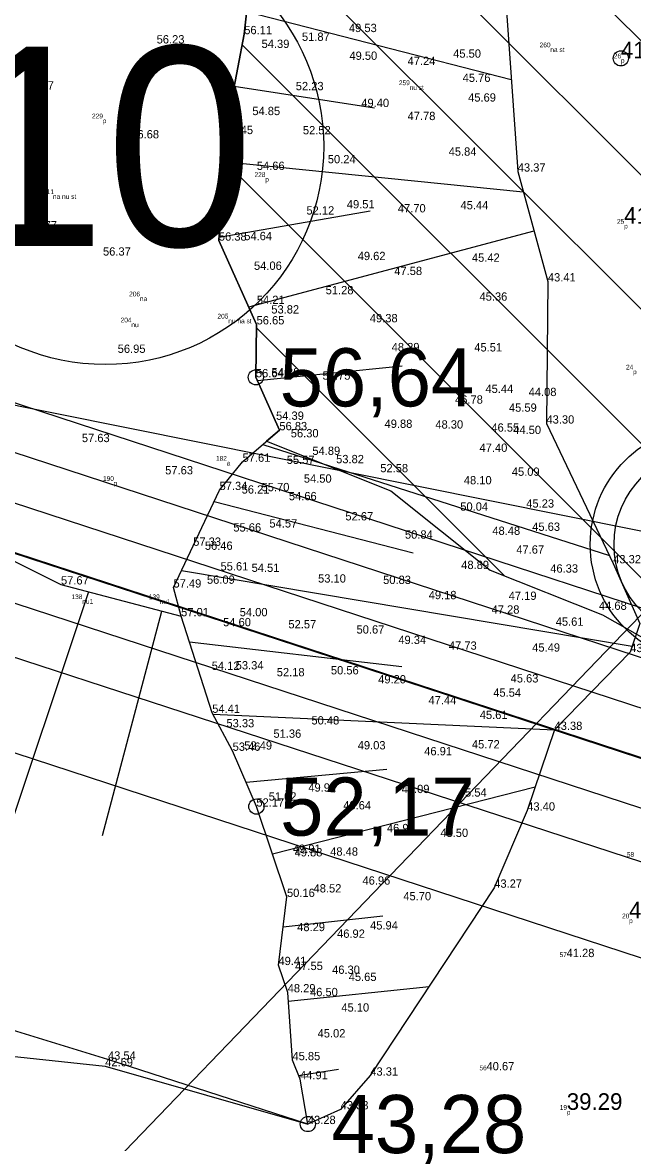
# Model space of a CAD drawing. Extents: x 700746 to 706058, y 6570320 to 6580460.
# Drawn here: x 702872.73 to 702898.47, y 6577258.09 to 6577305.34 of the extents above; entities that cross this region are included whole.
import ezdxf

# ---------------------------------------------------------------- set-up
doc = ezdxf.new("R2010")
doc.units = 0
for name, color, linetype in [('GEOLPUNKT', 7, 'Continuous'), ('illumineerimisjooned', 7, 'Continuous'), ('Kaevandatud ala', 7, 'Continuous'), ('kataster', 7, 'Continuous'), ('KORGUS-EH2000', 7, 'Continuous'), ('Lõige', 7, 'Continuous'), ('maeeraldised_kehtivad', 7, 'Continuous'), ('MOOTKOOD', 7, 'Continuous'), ('MOOTKORG-EH2000', 7, 'Continuous'), ('MOOTNR', 7, 'Continuous'), ('mäeeraldis', 7, 'Continuous'), ('mäeeraldise teenindusmaa', 7, 'Continuous'), ('PIIR', 7, 'Continuous'), ('Plokid', 7, 'Continuous'), ('RELJEEF', 7, 'Continuous'), ('Tmaad_maeeraldised_kehtivad', 7, 'Continuous'), ('VEEKOGU', 7, 'Continuous'), ('VWX2_MV_PLOKK', 7, 'Continuous')]:
    doc.layers.add(name, color=color, linetype=linetype)

msp = doc.modelspace()

# ---------------------------------------------------------------- linework, layer by layer
at = {"layer": 'GEOLPUNKT'}
for radius in [5, 4]:
    msp.add_circle((702901.645, 6577283.339), radius, dxfattribs=at)
at = {"layer": 'illumineerimisjooned'}
for points in [[(702862.311, 6577373.596), (702850.89, 6577377.293), (702839.79, 6577379.563), (702831.646, 6577378.473), (702820.821, 6577374.823), (702754.92, 6577346.017), (702742.145, 6577342.939), (702732.615, 6577342.189), (702714.765, 6577344.588), (702715.658, 6577336.409), (703090.802, 6577213.589), (703232.719, 6577108.158), (703252.344, 6577093.719)], [(702976.891, 6576643.26), (702915.328, 6577059.558), (702785.772, 6577104.455), (702748.407, 6577249.47), (702721.642, 6577298.043), (702716.252, 6577332.033), (702861.102, 6577284.56), (703066.328, 6577217.365), (703088.858, 6577210.018), (703169.031, 6577150.466), (703230.271, 6577104.95), (703275.453, 6577071.675), (703358.033, 6576531.935)], [(703167.053, 6577159.433), (703091.733, 6577215.389), (702863.784, 6577290.018)], [(703290.041, 6576963.147), (703188.508, 6577001.438), (703016.934, 6577112.515), (702852.033, 6577230.395), (702862.776, 6577281.723), (703065.707, 6577215.464), (703087.928, 6577208.218), (703167.838, 6577148.861), (703229.081, 6577103.342), (703273.601, 6577070.555), (703290.041, 6576963.147)]]:
    msp.add_lwpolyline(points, dxfattribs=at)
at = {"layer": 'Kaevandatud ala'}
for p, q in [((702885.692, 6577317.651), (702961.786, 6577241.557)), ((702883.741, 6577313.945), (702957.002, 6577240.684)), ((702883.182, 6577308.847), (702952.218, 6577239.811)), ((702881.984, 6577304.388), (702946.502, 6577239.87)), ((702881.203, 6577299.512), (702938.426, 6577242.289)), ((702882.588, 6577292.47), (702893.053, 6577282.005))]:
    msp.add_line(p, q, dxfattribs=at)
for points in [[(702898.59, 6577340.48), (702896.67, 6577335.54), (702895.42, 6577329.91), (702892.39, 6577327.68), (702892.37, 6577325.56), (702890.6, 6577323.46), (702888.61, 6577321.22), (702886.48, 6577319.78), (702885.8, 6577318.02), (702885.43, 6577316.76), (702884.62, 6577315.21), (702883.8, 6577314.33), (702883.53, 6577312.58), (702883.4, 6577310.62), (702883.11, 6577308.26), (702882.2, 6577307.5), (702882.23, 6577306.39), (702882.07, 6577304.84), (702881.27, 6577300.63), (702881, 6577296.14), (702882.59, 6577292.61), (702882.56, 6577290.38), (702883.55, 6577288.15), (702883.006, 6577287.683)], [(702883.006, 6577287.683), (702888.247, 6577285.595), (702892.428, 6577282.254), (702897.16, 6577280.37), (702901.941, 6577277.664), (702901.603, 6577275.308), (702911.185, 6577268.859), (702910.984, 6577262.539), (702910.646, 6577251.884), (702919.266, 6577249.854), (702923.239, 6577243.427), (702932.999, 6577245.456), (702942.381, 6577239.981), (702951.761, 6577239.728), (702966.129, 6577242.349), (702973.059, 6577233.977), (702979.82, 6577236.43), (702989.2, 6577237.36), (702992.919, 6577234.147), (702996.289, 6577226.894), (703003.652, 6577221.631), (703013.709, 6577214.443)]]:
    msp.add_lwpolyline(points, dxfattribs=at)
at = {"layer": 'kataster'}
msp.add_lwpolyline([(702754.28, 6577347.92), (702820.1, 6577376.69), (702831.19, 6577380.43), (702839.86, 6577381.59), (702851.4, 6577379.23), (702863.2, 6577375.41), (702878.06, 6577370.59), (702900.72, 6577367.74), (702944.77, 6577367.92), (702961.68, 6577364.05), (703005.04, 6577344.66), (703019.19, 6577342.06), (703041.25, 6577339.7), (703057.1, 6577329.85), (703096.08, 6577280.59), (703119.31, 6577233.95), (703129.16, 6577218.59), (703141.54, 6577201.64), (703167.04, 6577172.32), (703168.73, 6577170.37), (703277.36, 6577072.83), (703231.53, 6577106.55), (703089.87, 6577211.79), (702713.81, 6577334.91)], dxfattribs=at)
msp.add_lwpolyline([(702852.27, 6575508.89), (702837.26, 6575620.73), (702848.38, 6575976.59), (702782.85, 6576063.35), (702782.57, 6576096.37), (702842.53, 6576210.56), (702853.4, 6576267.5), (702844.46, 6576489.93), (702877.29, 6576548.25), (702974.72, 6576643.9), (702913.57, 6577058.07), (702784.04, 6577102.84), (702746.48, 6577248.7), (702719.69, 6577297.36), (702713.81, 6577334.91), (703089.87, 6577211.79), (703231.53, 6577106.55), (703277.36, 6577072.83), (703360.09, 6576531.99), (703311.6, 6576228.52), (703293.62, 6575965.66), (703298.84, 6575573.29)], close=True, dxfattribs=at)
at = {"layer": 'KORGUS-EH2000'}
for centre in [(702897.935, 6577303.823), (702882.56, 6577290.38), (702882.58, 6577272.29), (702884.75, 6577258.91)]:
    msp.add_circle(centre, 0.32, dxfattribs=at)
at = {"layer": 'Lõige'}
for points in [[(702834.687, 6577213.734), (702849.883, 6577229.558), (702901.645, 6577283.339), (702934.372, 6577351.305), (702933.752, 6577409.378), (702972.502, 6577440.12), (702995.067, 6577474.124)], [(702840.34, 6577295.661), (702901.645, 6577283.339), (702991.177, 6577252.569), (703074.081, 6577220.567), (703131.906, 6577226.463), (703178.085, 6577224.803)]]:
    msp.add_lwpolyline(points, dxfattribs=at)
at = {"layer": 'maeeraldised_kehtivad'}
msp.add_lwpolyline([(702849.808, 6577229.527), (702861.724, 6577286.461), (703066.949, 6577219.266), (703089.789, 6577211.819), (703170.224, 6577152.072), (703231.46, 6577106.558), (703277.305, 6577072.795), (703294.683, 6576959.259), (703187.602, 6576999.642), (703015.809, 6577110.861)], close=True, dxfattribs=at)
at = {"layer": 'mäeeraldis'}
msp.add_lwpolyline([(702859.802, 6577465.696), (703119.425, 6577442.241), (703125.486, 6577438.859), (703125.878, 6577438.438), (703152.852, 6577264.176), (703167.04, 6577172.32), (703167.079, 6577172.263), (703170.22, 6577152.098), (703089.87, 6577211.79), (702861.725, 6577286.484), (702863.214, 6577375.336), (702862.386, 6577440.049), (702862.38, 6577440.109), (702862.38, 6577440.12), (702859.802, 6577465.696)], dxfattribs=at)
at = {"layer": 'mäeeraldise teenindusmaa'}
msp.add_lwpolyline([(702859.8, 6577465.72), (703125.43, 6577441.71), (703167.04, 6577172.32), (703168.73, 6577170.37), (703277.36, 6577072.83), (703231.53, 6577106.55), (703089.87, 6577211.79), (702713.81, 6577334.91), (702712.5, 6577346.91), (702732.67, 6577344.2), (702741.83, 6577344.92), (702754.28, 6577347.92), (702820.1, 6577376.69), (702831.19, 6577380.43), (702839.86, 6577381.59), (702851.4, 6577379.23), (702863.2, 6577375.41), (702862.38, 6577440.12), (702859.8, 6577465.72)], dxfattribs=at)
at = {"layer": 'PIIR'}
msp.add_circle((702876.218, 6577300.118), 9.2, dxfattribs=at)
at = {"layer": 'Plokid'}
msp.add_lwpolyline([(703043.339, 6577445.098), (703121.898, 6577438.001), (703148.899, 6577263.565), (703163.227, 6577170.805), (703163.267, 6577170.746), (703164.325, 6577163.951), (703092.665, 6577217.188), (702865.809, 6577291.46), (702867.214, 6577375.329), (702866.384, 6577440.28), (702866.378, 6577440.34), (702866.377, 6577440.346), (702864.268, 6577461.276), (703043.339, 6577445.098)], dxfattribs=at)
msp.add_lwpolyline([(703287.547, 6576966.226), (703189.415, 6577003.234), (703018.06, 6577114.169), (702854.258, 6577231.263), (702863.9, 6577277.331), (703064.465, 6577211.662), (703086.067, 6577204.618), (703165.453, 6577145.65), (703226.702, 6577100.127), (703272.178, 6577066.636)], close=True, dxfattribs=at)
at = {"layer": 'RELJEEF'}
for p, q in [((702882.168, 6577305.791), (702893.32, 6577302.93)), ((702887.559, 6577301.73), (702881.651, 6577302.635)), ((702881.2, 6577299.473), (702893.824, 6577298.196)), ((702887.377, 6577297.381), (702881.008, 6577296.279)), ((702882.257, 6577293.349), (702894.276, 6577296.549)), ((702888.728, 6577290.853), (702882.625, 6577290.235)), ((702882.852, 6577287.551), (702897.454, 6577282.867)), ((702889.186, 6577282.971), (702880.799, 6577285.14)), ((702879.433, 6577282.246), (702898.417, 6577279.056)), ((702875.506, 6577281.344), (702869.087, 6577262.109)), ((702876.096, 6577271.075), (702878.599, 6577280.525)), ((702888.714, 6577278.176), (702879.761, 6577279.22)), ((702880.753, 6577276.179), (702895.14, 6577275.52)), ((702888.074, 6577273.857), (702882.149, 6577273.303)), ((702883.253, 6577270.302), (702894.331, 6577273.129)), ((702887.909, 6577267.668), (702883.711, 6577267.213)), ((702883.926, 6577264.091), (702889.855, 6577264.705)), ((702886.043, 6577261.211), (702884.361, 6577260.947)), ((702884.75, 6577258.91), (702884.75, 6577258.91))]:
    msp.add_line(p, q, dxfattribs=at)
for points in [[(702884.75, 6577258.91), (702884.42, 6577260.8), (702884.1, 6577261.6), (702883.9, 6577264.46), (702883.51, 6577265.61), (702883.87, 6577268.48), (702882.58, 6577272.29), (702881.58, 6577274.64), (702880.72, 6577276.24), (702879.41, 6577280.31), (702879.09, 6577281.52), (702879.92, 6577283.28), (702881.03, 6577285.63), (702882, 6577286.82), (702883.55, 6577288.15), (702882.56, 6577290.38), (702882.59, 6577292.61), (702881, 6577296.14), (702881.27, 6577300.63), (702882.07, 6577304.84), (702882.23, 6577306.39)], [(702884.75, 6577258.91), (702884.42, 6577260.8), (702884.1, 6577261.6), (702883.9, 6577264.46), (702883.51, 6577265.61), (702883.87, 6577268.48), (702882.58, 6577272.29), (702881.58, 6577274.64), (702880.72, 6577276.24), (702879.41, 6577280.31), (702879.09, 6577281.52), (702879.92, 6577283.28), (702881.03, 6577285.63), (702882, 6577286.82), (702883.55, 6577288.15), (702882.56, 6577290.38), (702882.59, 6577292.61), (702881, 6577296.14), (702881.27, 6577300.63), (702882.07, 6577304.84), (702882.23, 6577306.39)], [(702739.023, 6577231.907), (702738.829, 6577234.118), (702736.843, 6577244.166), (702737.449, 6577253.091), (702740.127, 6577260.7), (702744.086, 6577271.721), (702753.189, 6577289.269), (702762.956, 6577297.622), (702781.322, 6577304.452), (702803.109, 6577295.631), (702808.823, 6577292.731), (702816.396, 6577293.218), (702820.373, 6577296.135), (702836.414, 6577289.932), (702856.388, 6577286.327), (702857.99, 6577287.14), (702860.42, 6577287.06), (702862.6, 6577287.41), (702864.79, 6577286.08), (702869.15, 6577284.23), (702874.35, 6577281.65), (702879.41, 6577280.31)], [(702788.861, 6577235.978), (702797.028, 6577259.824), (702799.555, 6577268.407), (702805.282, 6577267.438), (702829.907, 6577267.309), (702860.829, 6577262.996), (702876.211, 6577261.343), (702884.75, 6577258.91)]]:
    msp.add_lwpolyline(points, dxfattribs=at)
at = {"layer": 'Tmaad_maeeraldised_kehtivad'}
msp.add_lwpolyline([(702974.764, 6576643.974), (702913.527, 6577058.065), (702784.103, 6577102.917), (702746.534, 6577248.726), (702719.722, 6577297.384), (702713.764, 6577334.953), (702861.724, 6577286.461), (703066.949, 6577219.266), (703089.789, 6577211.819), (703089.789, 6577211.819), (703170.224, 6577152.072), (703231.46, 6577106.558), (703277.305, 6577072.795), (703360.057, 6576531.928)], dxfattribs=at)
at = {"layer": 'VEEKOGU'}
for points in [[(702899.52, 6577319.43), (702898.02, 6577316.02), (702896.85, 6577313.28), (702894.87, 6577309.23), (702893.12, 6577305.81), (702893.59, 6577299.05), (702894.86, 6577294.42), (702894.8, 6577288.43), (702897.61, 6577282.54), (702898.74, 6577280.01), (702898.33, 6577278.8), (702895.14, 6577275.52), (702893.99, 6577272.12), (702892.6, 6577268.87), (702887.38, 6577260.95), (702886.13, 6577259.53)], [(702899.52, 6577319.43), (702898.02, 6577316.02), (702896.85, 6577313.28), (702894.87, 6577309.23), (702893.12, 6577305.81), (702893.59, 6577299.05), (702894.86, 6577294.42), (702894.8, 6577288.43), (702897.61, 6577282.54), (702898.74, 6577280.01), (702898.33, 6577278.8), (702895.14, 6577275.52), (702893.99, 6577272.12), (702892.6, 6577268.87), (702887.38, 6577260.95), (702886.13, 6577259.53)], [(702886.13, 6577259.53), (702884.75, 6577258.91), (702876.329, 6577261.625), (702872.126, 6577262.92), (702866.842, 6577263.801), (702863.234, 6577263.318), (702860.829, 6577262.996), (702858.855, 6577263.15), (702853.034, 6577263.204), (702848.147, 6577263.29), (702841.101, 6577265.479), (702833.134, 6577264.702), (702830.471, 6577264.031), (702826.548, 6577262.778), (702820.531, 6577264.171), (702818.095, 6577266.211), (702814.068, 6577266.459)], [(702886.13, 6577259.53), (702884.75, 6577258.91), (702876.329, 6577261.625), (702872.126, 6577262.92), (702866.842, 6577263.801), (702863.234, 6577263.318), (702860.829, 6577262.996), (702858.855, 6577263.15), (702853.034, 6577263.204), (702848.147, 6577263.29), (702841.101, 6577265.479), (702833.134, 6577264.702), (702830.471, 6577264.031), (702826.548, 6577262.778), (702820.531, 6577264.171), (702818.095, 6577266.211), (702814.068, 6577266.459)]]:
    msp.add_lwpolyline(points, dxfattribs=at)
at = {"layer": 'VWX2_MV_PLOKK'}
for points in [[(702859.74, 6577465.7), (703125.37, 6577441.7), (703167.08, 6577172.26), (703170.22, 6577152.07), (703089.79, 6577211.82), (702861.72, 6577286.46), (702863.21, 6577375.33), (702862.39, 6577440.05)], [(702859.74, 6577465.7), (703125.37, 6577441.7), (703167.08, 6577172.26), (703170.22, 6577152.07), (703089.79, 6577211.82), (702861.72, 6577286.46), (702863.21, 6577375.33), (702862.39, 6577440.05)], [(702849.88, 6577229.56), (702861.72, 6577286.46), (703066.96, 6577219.29), (703089.79, 6577211.82), (703170.22, 6577152.07), (703231.53, 6577106.55), (703277.36, 6577072.83), (703294.74, 6576959.21), (703187.67, 6576999.67), (703015.74, 6577110.88)], [(702849.88, 6577229.56), (702861.72, 6577286.46), (703066.96, 6577219.29), (703089.79, 6577211.82), (703170.22, 6577152.07), (703231.53, 6577106.55), (703277.36, 6577072.83), (703294.74, 6576959.21), (703187.67, 6576999.67), (703015.74, 6577110.88)]]:
    msp.add_lwpolyline(points, close=True, dxfattribs=at)

# ---------------------------------------------------------------- texts
at = {"layer": 'KORGUS-EH2000'}
for s, p in [('56,64', (702883.56, 6577289.155)), ('52,17', (702883.58, 6577271.065)), ('43,28', (702885.75, 6577257.685))]:
    msp.add_text(s, height=2.45, dxfattribs=at).set_placement(p)
at = {"layer": 'MOOTKOOD'}
for s, p in [('na st', (702894.964, 6577304.089)), ('p', (702897.935, 6577303.623)), ('nu st', (702889.037, 6577302.493)), ('p', (702876.11, 6577301.092)), ('p', (702882.956, 6577298.621)), ('na nu st', (702874.01, 6577297.902)), ('p', (702898.071, 6577296.652)), ('na', (702877.673, 6577293.592)), ('nu na st', (702881.397, 6577292.657)), ('nu', (702877.314, 6577292.495)), ('p', (702898.448, 6577290.51)), ('a', (702881.329, 6577286.665)), ('p', (702876.572, 6577285.815)), ('nu1', (702875.247, 6577280.834)), ('nu1', (702878.506, 6577280.83)), ('p', (702898.281, 6577267.379)), ('p', (702895.657, 6577259.309))]:
    msp.add_text(s, height=0.2, dxfattribs=at).set_placement(p)
at = {"layer": 'MOOTKORG-EH2000'}
for s, height, p in [('56.11', 0.35, (702882.07, 6577304.84)), ('49.53', 0.35, (702886.48, 6577304.93)), ('56.23', 0.35, (702878.38, 6577304.45)), ('54.39', 0.35, (702882.8, 6577304.26)), ('51.87', 0.35, (702884.5, 6577304.56)), ('41.24', 0.7, (702897.935, 6577303.823)), ('49.50', 0.35, (702886.5, 6577303.76)), ('45.50', 0.35, (702890.87, 6577303.85)), ('47.24', 0.35, (702888.95, 6577303.54)), ('45.76', 0.35, (702891.27, 6577302.83)), ('57.07', 0.35, (702872.88, 6577302.51)), ('52.23', 0.35, (702884.24, 6577302.48)), ('45.69', 0.35, (702891.5, 6577302)), ('54.85', 0.35, (702882.41, 6577301.43)), ('49.40', 0.35, (702887, 6577301.77)), ('47.78', 0.35, (702888.95, 6577301.22)), ('56.68', 0.35, (702877.31, 6577300.45)), ('56.45', 0.35, (702881.27, 6577300.63)), ('52.52', 0.35, (702884.54, 6577300.62)), ('45.84', 0.35, (702890.68, 6577299.72)), ('54.66', 0.35, (702882.6, 6577299.12)), ('50.24', 0.35, (702885.59, 6577299.4)), ('43.37', 0.35, (702893.59, 6577299.05)), ('52.12', 0.35, (702884.69, 6577297.24)), ('49.51', 0.35, (702886.39, 6577297.5)), ('47.70', 0.35, (702888.54, 6577297.33)), ('45.44', 0.35, (702891.18, 6577297.46)), ('41.35', 0.7, (702898.071, 6577296.852)), ('56.77', 0.35, (702873.01, 6577296.62)), ('56.38', 0.35, (702881, 6577296.14)), ('54.64', 0.35, (702882.07, 6577296.16)), ('56.37', 0.35, (702876.12, 6577295.51)), ('49.62', 0.35, (702886.85, 6577295.32)), ('45.42', 0.35, (702891.66, 6577295.25)), ('54.06', 0.35, (702882.48, 6577294.91)), ('47.58', 0.35, (702888.39, 6577294.69)), ('43.41', 0.35, (702894.86, 6577294.42)), ('51.28', 0.35, (702885.5, 6577293.88)), ('54.21', 0.35, (702882.6, 6577293.47)), ('45.36', 0.35, (702891.98, 6577293.61)), ('53.82', 0.35, (702883.21, 6577293.07)), ('56.65', 0.35, (702882.59, 6577292.61)), ('49.38', 0.35, (702887.36, 6577292.7)), ('56.95', 0.35, (702876.74, 6577291.41)), ('48.29', 0.35, (702888.28, 6577291.48)), ('45.51', 0.35, (702891.76, 6577291.47)), ('56.64', 0.35, (702882.56, 6577290.38)), ('54.28', 0.35, (702883.22, 6577290.42)), ('51.75', 0.35, (702885.37, 6577290.28)), ('45.44', 0.35, (702892.23, 6577289.72)), ('44.08', 0.35, (702894.05, 6577289.59)), ('46.78', 0.35, (702890.95, 6577289.27)), ('54.39', 0.35, (702883.41, 6577288.59)), ('45.59', 0.35, (702893.22, 6577288.93)), ('56.83', 0.35, (702883.55, 6577288.15)), ('49.88', 0.35, (702887.98, 6577288.25)), ('48.30', 0.35, (702890.12, 6577288.22)), ('46.55', 0.35, (702892.48, 6577288.09)), ('43.30', 0.35, (702894.8, 6577288.43)), ('57.63', 0.35, (702875.23, 6577287.65)), ('56.30', 0.35, (702884.03, 6577287.85)), ('44.50', 0.35, (702893.4, 6577287.99)), ('47.40', 0.35, (702891.98, 6577287.24)), ('57.61', 0.35, (702882, 6577286.82)), ('55.57', 0.35, (702883.86, 6577286.73)), ('54.89', 0.35, (702884.94, 6577287.11)), ('53.82', 0.35, (702885.94, 6577286.76)), ('57.63', 0.35, (702878.74, 6577286.29)), ('52.58', 0.35, (702887.8, 6577286.38)), ('45.09', 0.35, (702893.34, 6577286.23)), ('54.50', 0.35, (702884.58, 6577285.94)), ('48.10', 0.35, (702891.32, 6577285.87)), ('57.34', 0.35, (702881.03, 6577285.63)), ('56.21', 0.35, (702881.96, 6577285.48)), ('55.70', 0.35, (702882.8, 6577285.58)), ('54.66', 0.35, (702883.95, 6577285.2)), ('45.23', 0.35, (702893.95, 6577284.89)), ('52.67', 0.35, (702886.33, 6577284.35)), ('50.04', 0.35, (702891.17, 6577284.76)), ('55.66', 0.35, (702881.61, 6577283.88)), ('54.57', 0.35, (702883.13, 6577284.05)), ('45.63', 0.35, (702894.2, 6577283.91)), ('50.84', 0.35, (702888.84, 6577283.58)), ('48.48', 0.35, (702892.52, 6577283.74)), ('57.33', 0.35, (702879.92, 6577283.28)), ('56.46', 0.35, (702880.41, 6577283.11)), ('47.67', 0.35, (702893.53, 6577282.95)), ('43.32', 0.35, (702897.61, 6577282.54)), ('55.61', 0.35, (702881.07, 6577282.24)), ('54.51', 0.35, (702882.38, 6577282.18)), ('48.89', 0.35, (702891.21, 6577282.3)), ('46.33', 0.35, (702894.96, 6577282.15)), ('57.67', 0.35, (702874.35, 6577281.65)), ('57.49', 0.35, (702879.09, 6577281.52)), ('56.09', 0.35, (702880.5, 6577281.68)), ('53.10', 0.35, (702885.18, 6577281.73)), ('50.83', 0.35, (702887.92, 6577281.67)), ('49.18', 0.35, (702889.84, 6577281.03)), ('47.19', 0.35, (702893.21, 6577281)), ('44.68', 0.35, (702897.01, 6577280.58)), ('57.01', 0.35, (702879.41, 6577280.31)), ('54.00', 0.35, (702881.88, 6577280.31)), ('47.28', 0.35, (702892.49, 6577280.42)), ('54.60', 0.35, (702881.18, 6577279.89)), ('52.57', 0.35, (702883.93, 6577279.8)), ('45.61', 0.35, (702895.19, 6577279.91)), ('50.67', 0.35, (702886.8, 6577279.58)), ('49.34', 0.35, (702888.56, 6577279.14)), ('47.73', 0.35, (702890.69, 6577278.9)), ('45.49', 0.35, (702894.2, 6577278.82)), ('43.38', 0.35, (702898.33, 6577278.8)), ('54.12', 0.35, (702880.7, 6577278.05)), ('53.34', 0.35, (702881.71, 6577278.07)), ('52.18', 0.35, (702883.44, 6577277.78)), ('50.56', 0.35, (702885.72, 6577277.86)), ('49.20', 0.35, (702887.71, 6577277.48)), ('45.63', 0.35, (702893.29, 6577277.52)), ('45.54', 0.35, (702892.56, 6577276.92)), ('47.44', 0.35, (702889.83, 6577276.6)), ('54.41', 0.35, (702880.72, 6577276.24)), ('45.61', 0.35, (702891.99, 6577275.98)), ('53.33', 0.35, (702881.32, 6577275.63)), ('50.48', 0.35, (702884.9, 6577275.75)), ('43.38', 0.35, (702895.14, 6577275.52)), ('51.36', 0.35, (702883.3, 6577275.19)), ('53.46', 0.35, (702881.58, 6577274.64)), ('52.49', 0.35, (702882.07, 6577274.69)), ('49.03', 0.35, (702886.85, 6577274.7)), ('46.91', 0.35, (702889.65, 6577274.45)), ('45.72', 0.35, (702891.66, 6577274.74)), ('51.02', 0.35, (702883.1, 6577272.54)), ('49.92', 0.35, (702884.77, 6577272.92)), ('47.09', 0.35, (702888.7, 6577272.86)), ('45.54', 0.35, (702891.11, 6577272.71)), ('52.17', 0.35, (702882.58, 6577272.29)), ('48.64', 0.35, (702886.24, 6577272.17)), ('43.40', 0.35, (702893.99, 6577272.12)), ('46.99', 0.35, (702888.08, 6577271.21)), ('45.50', 0.35, (702890.33, 6577271.01)), ('49.91', 0.35, (702884.12, 6577270.34)), ('49.88', 0.35, (702884.19, 6577270.19)), ('48.48', 0.35, (702885.69, 6577270.22)), ('46.96', 0.35, (702887.05, 6577269)), ('43.27', 0.35, (702892.6, 6577268.87)), ('50.16', 0.35, (702883.87, 6577268.48)), ('48.52', 0.35, (702884.99, 6577268.67)), ('45.70', 0.35, (702888.77, 6577268.34)), ('40.07', 0.7, (702898.281, 6577267.579)), ('48.29', 0.35, (702884.3, 6577267.04)), ('45.94', 0.35, (702887.37, 6577267.11)), ('46.92', 0.35, (702885.98, 6577266.76)), ('41.28', 0.35, (702895.649, 6577265.947)), ('49.41', 0.35, (702883.51, 6577265.61)), ('47.55', 0.35, (702884.21, 6577265.4)), ('46.30', 0.35, (702885.77, 6577265.24)), ('45.65', 0.35, (702886.47, 6577264.94)), ('48.29', 0.35, (702883.9, 6577264.46)), ('46.50', 0.35, (702884.84, 6577264.3)), ('45.10', 0.35, (702886.16, 6577263.65)), ('45.02', 0.35, (702885.16, 6577262.56)), ('42.69', 0.35, (702876.211, 6577261.343)), ('43.54', 0.35, (702876.329, 6577261.625)), ('45.85', 0.35, (702884.1, 6577261.6)), ('40.67', 0.35, (702892.275, 6577261.175)), ('44.91', 0.35, (702884.42, 6577260.8)), ('43.31', 0.35, (702887.38, 6577260.95)), ('39.29', 0.7, (702895.657, 6577259.509)), ('43.33', 0.35, (702886.13, 6577259.53)), ('43.28', 0.35, (702884.75, 6577258.91))]:
    msp.add_text(s, height=height, dxfattribs=at).set_placement(p)
at = {"layer": 'MOOTNR'}
for s, p in [('260', (702894.511, 6577304.289)), ('26', (702897.637, 6577303.823)), ('259', (702888.583, 6577302.693)), ('229', (702875.656, 6577301.292)), ('228', (702882.502, 6577298.821)), ('211', (702873.595, 6577298.102)), ('25', (702897.771, 6577296.852)), ('206', (702877.22, 6577293.792)), ('204', (702876.862, 6577292.695)), ('205', (702880.942, 6577292.857)), ('24', (702898.151, 6577290.71)), ('182', (702880.878, 6577286.865)), ('190', (702876.119, 6577286.015)), ('138', (702874.793, 6577281.034)), ('139', (702878.052, 6577281.03)), ('58', (702898.183, 6577270.173)), ('20', (702897.984, 6577267.579)), ('57', (702895.351, 6577265.947)), ('56', (702891.977, 6577261.175)), ('19', (702895.359, 6577259.509))]:
    msp.add_text(s, height=0.2, dxfattribs=at).set_placement(p)
at = {"layer": 'PIIR'}
msp.add_text('10', height=8.4, dxfattribs=at).set_placement((702869.982, 6577295.918))

doc.saveas('drawing.dxf')
